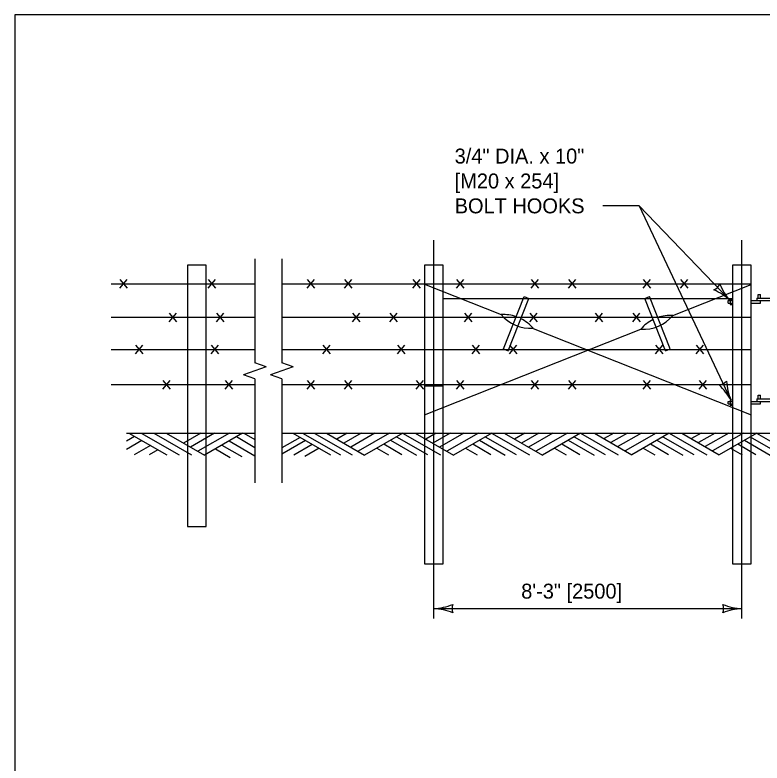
# Model space of a CAD drawing. Extents: x 49991.4 to 50021, y 49987.6 to 50011.4.
# Drawn here: x 50000.336 to 50003.336, y 50008.258 to 50011.263 of the extents above; entities that cross this region are included whole.
import ezdxf

# ---------------------------------------------------------------- set-up
doc = ezdxf.new("R2010")
doc.units = 0
for name, color, linetype in [('Level 1', 7, 'Continuous'), ('Level 2', 7, 'Continuous'), ('Level 3', 7, 'Continuous'), ('Level 4', 7, 'Continuous'), ('Level 5', 7, 'Continuous'), ('Level 6', 7, 'Continuous')]:
    doc.layers.add(name, color=color, linetype=linetype)

msp = doc.modelspace()

# ---------------------------------------------------------------- linework, layer by layer
at = {"layer": 'Level 1'}
for p, q in [((50001.029, 50010.2583), (50001.029, 50009.5833)), ((50001.104, 50010.2583), (50001.029, 50010.2583)), ((50001.104, 50009.5833), (50001.104, 50010.2583)), ((50001.9802, 50010.2583), (50001.9802, 50009.5833)), ((50002.0552, 50010.2583), (50001.9802, 50010.2583)), ((50002.0552, 50009.5833), (50002.0552, 50010.2583)), ((50003.2177, 50010.2583), (50003.2177, 50009.5833)), ((50003.2927, 50010.2583), (50003.2177, 50010.2583)), ((50003.2927, 50009.5833), (50003.2927, 50010.2583)), ((50000.7567, 50010.1652), (50000.7861, 50010.1999)), ((50000.7874, 50010.1652), (50000.7581, 50010.1999)), ((50001.1117, 50010.1652), (50001.1411, 50010.1999)), ((50001.1424, 50010.1652), (50001.1131, 50010.1999)), ((50001.5087, 50010.1652), (50001.5381, 50010.1999)), ((50001.5394, 50010.1652), (50001.5101, 50010.1999)), ((50001.6587, 50010.1652), (50001.6881, 50010.1999)), ((50001.6894, 50010.1652), (50001.6601, 50010.1999)), ((50001.9341, 50010.1652), (50001.9635, 50010.1999)), ((50001.9648, 50010.1652), (50001.9355, 50010.1999)), ((50002.1087, 50010.1652), (50002.1381, 50010.1999)), ((50002.1394, 50010.1652), (50002.1101, 50010.1999)), ((50002.4087, 50010.1652), (50002.4381, 50010.1999)), ((50002.4394, 50010.1652), (50002.4101, 50010.1999)), ((50002.5587, 50010.1652), (50002.5881, 50010.1999)), ((50002.5894, 50010.1652), (50002.5601, 50010.1999)), ((50002.8587, 50010.1652), (50002.8881, 50010.1999)), ((50002.8894, 50010.1652), (50002.8601, 50010.1999)), ((50003.0087, 50010.1652), (50003.0381, 50010.1999)), ((50003.0394, 50010.1652), (50003.0101, 50010.1999)), ((50000.7219, 50010.1833), (50001.2994, 50010.1833)), ((50001.4073, 50010.1833), (50003.2927, 50010.1833)), ((50001.9802, 50010.1811), (50002.2883, 50010.0591)), ((50002.0552, 50010.1833), (50003.2177, 50010.1833)), ((50002.9776, 50010.0556), (50003.2927, 50010.1803)), ((50002.2982, 50009.9217), (50002.3814, 50010.1317)), ((50002.3814, 50010.1317), (50002.4, 50010.1243)), ((50002.8652, 50010.1243), (50002.8838, 50010.1317)), ((50002.967, 50009.9217), (50002.8838, 50010.1317)), ((50003.3202, 50010.1253), (50003.3202, 50010.1403)), ((50003.3202, 50010.1403), (50003.3302, 50010.1403)), ((50003.3302, 50010.1253), (50003.3302, 50010.1403)), ((50002.0552, 50010.1233), (50003.2177, 50010.1233)), ((50002.3168, 50009.9143), (50002.4, 50010.1243)), ((50002.9485, 50009.9143), (50002.8652, 50010.1243)), ((50003.2001, 50010.1053), (50003.2001, 50010.1153)), ((50003.2001, 50010.1153), (50003.2177, 50010.1153)), ((50003.2001, 50010.1053), (50003.2177, 50010.1053)), ((50003.2177, 50010.1203), (50003.2077, 50010.1203)), ((50003.2077, 50010.1203), (50003.2077, 50010.1003)), ((50003.2927, 50010.1153), (50003.5152, 50010.1153)), ((50003.2927, 50010.1053), (50003.3302, 50010.1053)), ((50003.3152, 50010.1253), (50003.5152, 50010.1253)), ((50003.3152, 50010.1253), (50003.3152, 50010.1153)), ((50003.3302, 50010.1053), (50003.3302, 50010.1153)), ((50003.2077, 50010.1003), (50003.2177, 50010.1003)), ((50000.7219, 50010.0483), (50001.2994, 50010.0483)), ((50000.9553, 50010.0302), (50000.9846, 50010.0649)), ((50000.986, 50010.0302), (50000.9566, 50010.0649)), ((50001.1446, 50010.0302), (50001.1739, 50010.0649)), ((50001.1753, 50010.0302), (50001.1459, 50010.0649)), ((50001.4073, 50010.0483), (50003.2927, 50010.0483)), ((50001.6916, 50010.0302), (50001.7209, 50010.0649)), ((50001.7223, 50010.0302), (50001.6929, 50010.0649)), ((50001.8416, 50010.0302), (50001.8709, 50010.0649)), ((50001.8723, 50010.0302), (50001.8429, 50010.0649)), ((50002.1416, 50010.0302), (50002.1709, 50010.0649)), ((50002.1723, 50010.0302), (50002.1429, 50010.0649)), ((50002.4041, 50010.0302), (50002.4334, 50010.0649)), ((50002.4348, 50010.0302), (50002.4054, 50010.0649)), ((50002.6666, 50010.0302), (50002.6959, 50010.0649)), ((50002.6973, 50010.0302), (50002.6679, 50010.0649)), ((50002.8166, 50010.0302), (50002.8459, 50010.0649)), ((50002.8473, 50010.0302), (50002.8179, 50010.0649)), ((50001.9802, 50009.6565), (50002.8492, 50010.0005)), ((50002.4168, 50010.004), (50003.2927, 50009.6571)), ((50000.8196, 50009.9014), (50000.8489, 50009.9361)), ((50000.8503, 50009.9014), (50000.8209, 50009.9361)), ((50001.1236, 50009.9012), (50001.1529, 50009.9359)), ((50001.1543, 50009.9012), (50001.1249, 50009.9359)), ((50001.5716, 50009.9012), (50001.6009, 50009.9359)), ((50001.6023, 50009.9012), (50001.5729, 50009.9359)), ((50001.8716, 50009.9012), (50001.9009, 50009.9359)), ((50001.9023, 50009.9012), (50001.8729, 50009.9359)), ((50002.1716, 50009.9012), (50002.2009, 50009.9359)), ((50002.2023, 50009.9012), (50002.1729, 50009.9359)), ((50002.2982, 50009.9217), (50002.3168, 50009.9143)), ((50002.3216, 50009.9012), (50002.3509, 50009.9359)), ((50002.3523, 50009.9012), (50002.3229, 50009.9359)), ((50002.9086, 50009.9012), (50002.9379, 50009.9359)), ((50002.9393, 50009.9012), (50002.9099, 50009.9359)), ((50002.9485, 50009.9143), (50002.967, 50009.9217)), ((50003.0716, 50009.9012), (50003.1009, 50009.9359)), ((50003.1023, 50009.9012), (50003.0729, 50009.9359)), ((50000.7219, 50009.9193), (50001.2994, 50009.9193)), ((50001.4073, 50009.9193), (50003.2927, 50009.9193)), ((50000.7219, 50009.7783), (50001.2994, 50009.7783)), ((50000.9295, 50009.7602), (50000.9589, 50009.7949)), ((50000.9602, 50009.7602), (50000.9309, 50009.7949)), ((50001.1795, 50009.7602), (50001.2089, 50009.7949)), ((50001.2102, 50009.7602), (50001.1809, 50009.7949)), ((50001.4073, 50009.7783), (50003.2927, 50009.7783)), ((50001.5087, 50009.7602), (50001.5381, 50009.7949)), ((50001.5394, 50009.7602), (50001.5101, 50009.7949)), ((50001.6587, 50009.7602), (50001.6881, 50009.7949)), ((50001.6894, 50009.7602), (50001.6601, 50009.7949)), ((50001.9475, 50009.7602), (50001.9769, 50009.7949)), ((50001.9782, 50009.7602), (50001.9489, 50009.7949)), ((50001.9802, 50009.7728), (50002.0552, 50009.7728)), ((50002.1087, 50009.7602), (50002.1381, 50009.7949)), ((50002.1394, 50009.7602), (50002.1101, 50009.7949)), ((50002.4087, 50009.7602), (50002.4381, 50009.7949)), ((50002.4394, 50009.7602), (50002.4101, 50009.7949)), ((50002.5587, 50009.7602), (50002.5881, 50009.7949)), ((50002.5894, 50009.7602), (50002.5601, 50009.7949)), ((50002.8587, 50009.7602), (50002.8881, 50009.7949)), ((50002.8894, 50009.7602), (50002.8601, 50009.7949)), ((50003.0837, 50009.7602), (50003.1131, 50009.7949)), ((50003.1144, 50009.7602), (50003.0851, 50009.7949)), ((50003.2001, 50009.7002), (50003.2001, 50009.7102)), ((50003.2001, 50009.7102), (50003.2177, 50009.7102)), ((50003.2177, 50009.7152), (50003.2077, 50009.7152)), ((50003.2077, 50009.7152), (50003.2077, 50009.6952)), ((50003.2927, 50009.7102), (50003.5152, 50009.7102)), ((50003.3152, 50009.7202), (50003.5152, 50009.7202)), ((50003.3152, 50009.7202), (50003.3152, 50009.7102)), ((50003.3202, 50009.7202), (50003.3202, 50009.7352)), ((50003.3202, 50009.7352), (50003.3302, 50009.7352)), ((50003.3302, 50009.7202), (50003.3302, 50009.7352)), ((50003.3302, 50009.7002), (50003.3302, 50009.7102)), ((50003.2001, 50009.7002), (50003.2177, 50009.7002)), ((50003.2077, 50009.6952), (50003.2177, 50009.6952)), ((50003.2927, 50009.7002), (50003.3302, 50009.7002)), ((50000.7829, 50009.5833), (50001.2994, 50009.5833)), ((50000.8163, 50009.5698), (50000.7829, 50009.5505)), ((50000.7929, 50009.5833), (50000.9451, 50009.4954)), ((50000.8429, 50009.5833), (50000.9951, 50009.4954)), ((50000.8929, 50009.5833), (50001.0451, 50009.4954)), ((50000.9429, 50009.5833), (50001.0963, 50009.4947)), ((50001.0824, 50009.5833), (50001.0126, 50009.5431)), ((50001.1376, 50009.5833), (50001.0402, 50009.5271)), ((50001.1967, 50009.5833), (50001.0698, 50009.51)), ((50001.2497, 50009.5833), (50001.0963, 50009.4947)), ((50001.225, 50009.569), (50001.2994, 50009.5259)), ((50001.2545, 50009.5833), (50001.2994, 50009.5573)), ((50001.4073, 50009.5833), (50004.5539, 50009.5833)), ((50001.4809, 50009.5662), (50001.4073, 50009.5237)), ((50001.4512, 50009.5833), (50001.6034, 50009.4954)), ((50001.4905, 50009.5833), (50001.6427, 50009.4954)), ((50001.5375, 50009.5833), (50001.6897, 50009.4954)), ((50001.5866, 50009.5833), (50001.74, 50009.4947)), ((50001.67, 50009.5833), (50001.6283, 50009.5592)), ((50001.7261, 50009.5833), (50001.6563, 50009.5431)), ((50001.7813, 50009.5833), (50001.6839, 50009.5271)), ((50001.8404, 50009.5833), (50001.7135, 50009.51)), ((50001.8934, 50009.5833), (50001.74, 50009.4947)), ((50001.8677, 50009.5684), (50001.992, 50009.4966)), ((50001.8926, 50009.5833), (50002.0448, 50009.4954)), ((50001.9436, 50009.5833), (50002.097, 50009.4947)), ((50002.027, 50009.5833), (50001.9853, 50009.5592)), ((50002.0831, 50009.5833), (50002.0133, 50009.5431)), ((50002.1383, 50009.5833), (50002.0409, 50009.5271)), ((50002.1974, 50009.5833), (50002.0705, 50009.51)), ((50002.2504, 50009.5833), (50002.097, 50009.4947)), ((50002.2247, 50009.5684), (50002.349, 50009.4966)), ((50002.2496, 50009.5833), (50002.4018, 50009.4954)), ((50002.3006, 50009.5833), (50002.454, 50009.4947)), ((50002.384, 50009.5833), (50002.3423, 50009.5592)), ((50002.4401, 50009.5833), (50002.3703, 50009.5431)), ((50002.4953, 50009.5833), (50002.3979, 50009.5271)), ((50002.5544, 50009.5833), (50002.4275, 50009.51)), ((50002.6074, 50009.5833), (50002.454, 50009.4947)), ((50002.5817, 50009.5684), (50002.706, 50009.4966)), ((50002.6066, 50009.5833), (50002.7588, 50009.4954)), ((50002.6627, 50009.5833), (50002.8132, 50009.4964)), ((50002.7402, 50009.5833), (50002.7015, 50009.5609)), ((50002.7963, 50009.5833), (50002.7294, 50009.5448)), ((50002.8515, 50009.5833), (50002.7571, 50009.5288)), ((50002.9106, 50009.5833), (50002.7867, 50009.5117)), ((50002.9636, 50009.5833), (50002.8132, 50009.4964)), ((50002.9379, 50009.5684), (50003.0622, 50009.4966)), ((50002.9628, 50009.5833), (50003.115, 50009.4954)), ((50003.0138, 50009.5833), (50003.1643, 50009.4964)), ((50003.0913, 50009.5833), (50003.0526, 50009.5609)), ((50003.1474, 50009.5833), (50003.0805, 50009.5448)), ((50003.2026, 50009.5833), (50003.1082, 50009.5288)), ((50003.2617, 50009.5833), (50003.1378, 50009.5117)), ((50003.3147, 50009.5833), (50003.1643, 50009.4964)), ((50003.289, 50009.5684), (50003.4133, 50009.4966)), ((50003.3139, 50009.5833), (50003.4661, 50009.4954)), ((50000.845, 50009.5532), (50000.7829, 50009.5174)), ((50000.8794, 50009.5333), (50000.8137, 50009.4954)), ((50001.1667, 50009.5354), (50001.2462, 50009.4895)), ((50001.1961, 50009.5519), (50001.2994, 50009.4923)), ((50001.5025, 50009.5537), (50001.4073, 50009.4987)), ((50001.5299, 50009.5379), (50001.4556, 50009.495)), ((50001.8177, 50009.5396), (50001.8899, 50009.4978)), ((50001.844, 50009.5548), (50001.948, 50009.4947)), ((50002.1747, 50009.5396), (50002.2469, 50009.4978)), ((50002.201, 50009.5548), (50002.305, 50009.4947)), ((50002.5317, 50009.5396), (50002.6039, 50009.4978)), ((50002.558, 50009.5548), (50002.662, 50009.4947)), ((50002.8879, 50009.5396), (50002.9601, 50009.4978)), ((50002.9142, 50009.5548), (50003.0182, 50009.4947)), ((50003.239, 50009.5396), (50003.3112, 50009.4978)), ((50003.2653, 50009.5548), (50003.3693, 50009.4947)), ((50000.9096, 50009.5159), (50000.874, 50009.4954)), ((50001.1404, 50009.5202), (50001.2, 50009.4857)), ((50001.5572, 50009.5221), (50001.5003, 50009.4893)), ((50001.7884, 50009.5227), (50001.8355, 50009.4954)), ((50002.1457, 50009.5225), (50002.1925, 50009.4954)), ((50002.5024, 50009.5227), (50002.5495, 50009.4954)), ((50002.8586, 50009.5227), (50002.9057, 50009.4954)), ((50003.2097, 50009.5227), (50003.2568, 50009.4954))]:
    msp.add_line(p, q, dxfattribs=at)
msp.add_lwpolyline([(50008.6146, 50011.2628), (50000.3356, 50011.2628), (50000.3356, 50000.0624), (50008.6146, 50000.0624)], close=True, dxfattribs=at)
for centre, start, end in [((50002.298, 50009.9044), 70.692, 93.5951), ((50002.4071, 50010.1588), 220.0078, 273.5951), ((50002.298, 50009.9044), 40.0078, 63.2871), ((50002.8588, 50010.1552), 266.4347, 320.0376), ((50002.968, 50009.9009), 86.4347, 109.12), ((50002.968, 50009.9009), 116.5245, 140.0376)]:
    msp.add_arc(centre, 0.155, start, end, dxfattribs=at)
at = {"layer": 'Level 3'}
for p, q in [((50002.8429, 50010.496), (50002.6963, 50010.496)), ((50003.2077, 50010.1153), (50002.8429, 50010.496)), ((50002.8429, 50010.496), (50003.2112, 50009.7152)), ((50002.0177, 50008.8783), (50003.2552, 50008.8783))]:
    msp.add_line(p, q, dxfattribs=at)
for centre, radius, start, end in [((50003.119, 50010.2079), 0.0548, 295.9106, 331.633), ((50003.3744, 50010.2624), 0.2223, 201.2278, 221.4113), ((50003.0476, 50009.946), 0.233, 46.5991, 65.8489), ((50003.1565, 50009.8312), 0.0548, 277.3905, 313.1129), ((50003.0056, 50009.6055), 0.233, 28.079, 47.3289), ((50003.416, 50009.8017), 0.2223, 182.7077, 202.8912), ((50002.0062, 50009.111), 0.233, 272.8273, 292.0772), ((50002.0085, 50008.6562), 0.2223, 67.456, 87.6395), ((50002.1459, 50008.8783), 0.0548, 162.1388, 197.8612), ((50003.2644, 50009.1004), 0.2223, 247.456, 267.6395), ((50003.127, 50008.8783), 0.0548, 342.1388, 17.8612), ((50003.2667, 50008.6456), 0.233, 92.8273, 112.0772)]:
    msp.add_arc(centre, radius, start, end, dxfattribs=at)
at = {"layer": 'Level 4'}
for p, q in [((50001.029, 50009.5833), (50001.029, 50009.2083)), ((50001.104, 50009.2083), (50001.104, 50009.5833)), ((50001.9802, 50009.5833), (50001.9802, 50009.0583)), ((50002.0552, 50009.0583), (50002.0552, 50009.5833)), ((50003.2177, 50009.5833), (50003.2177, 50009.0583)), ((50003.2927, 50009.0583), (50003.2927, 50009.5833)), ((50001.029, 50009.2083), (50001.104, 50009.2083)), ((50001.9802, 50009.0583), (50002.0552, 50009.0583)), ((50003.2177, 50009.0583), (50003.2927, 50009.0583))]:
    msp.add_line(p, q, dxfattribs=at)
at = {"layer": 'Level 5'}
for p, q in [((50002.0177, 50008.8383), (50002.0177, 50010.3583)), ((50003.2552, 50008.8383), (50003.2552, 50010.3583))]:
    msp.add_line(p, q, dxfattribs=at)
at = {"layer": 'Level 6'}
for p, q in [((50001.2994, 50010.2833), (50001.2994, 50009.8657)), ((50001.4073, 50010.2833), (50001.4073, 50009.8657)), ((50001.3451, 50009.8495), (50001.2994, 50009.8657)), ((50001.453, 50009.8495), (50001.4073, 50009.8657)), ((50001.2994, 50009.8333), (50001.2537, 50009.8171)), ((50001.3451, 50009.8495), (50001.2994, 50009.8333)), ((50001.4073, 50009.8333), (50001.3616, 50009.8171)), ((50001.453, 50009.8495), (50001.4073, 50009.8333)), ((50001.2994, 50009.8009), (50001.2537, 50009.8171)), ((50001.2994, 50009.8009), (50001.2994, 50009.3833)), ((50001.4073, 50009.8009), (50001.3616, 50009.8171)), ((50001.4073, 50009.8009), (50001.4073, 50009.3833))]:
    msp.add_line(p, q, dxfattribs=at)

# ---------------------------------------------------------------- texts
at = {"layer": 'Level 2'}
for s, p in [('3/4" DIA. x 10"', (50002.1016, 50010.666)), ('[M20 x 254]', (50002.1016, 50010.566)), ('BOLT HOOKS', (50002.1016, 50010.466)), ('8\'-3" [2500]', (50002.3689, 50008.9183))]:
    msp.add_text(s, height=0.06, dxfattribs=at).set_placement(p)

doc.saveas('drawing.dxf')
